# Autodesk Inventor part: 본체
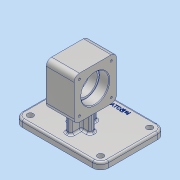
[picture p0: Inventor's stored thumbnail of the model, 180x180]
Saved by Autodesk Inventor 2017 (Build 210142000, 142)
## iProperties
Part Number: 본체
Material: 알루미늄 6061
Document SubType Name: Modeling
Designer: mrc
Density: 2.7 g/cm^3
Appearance: 알루미늄 - 평지
Mass: 683.214 g
Surface Area: 542.794 cm^2
Volume: 253.042 cm^3
Author: mrc
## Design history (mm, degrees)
sketch "스케치1"
  geometry: L1 (-65, -49)-(65, -49); L2 (65, -49)-(65, 49); L3 (65, 49)-(-65, 49); L4 (-65, 49)-(-65, -49); L5 (-65, -49)-(65, 49); L6 (65, -49)-(-65, 49); 1 further point
  constraints: 12 end point, 2 midpoint, 2 parallel, 1 horizontal, 1 perpendicular
  dimensions: "d0" = 130 distance of L2.end L3.end; "d1" = 98 distance of L1.end L2.end
extrude "돌출1" new body sketch "스케치1" distance "d2" = 10; taper "d3" = 0 deg
node "작업 평면1"
sketch "스케치2"
  geometry: L1 (-21, 19)-(21, 19); L2 (21, 19)-(21, -45); L3 (21, -45)-(-21, -45); L4 (-21, -45)-(-21, 19); L5 (-21, 19)-(21, -45); L6 (21, 19)-(-21, -45); L7 (65, -49)-(65, 49) reference; L8 (65, 49)-(-65, 49) reference; 2 further points
  constraints: 12 end point, 2 midpoint, 2 parallel, 1 horizontal, 1 perpendicular
  dimensions: "d5" = 42 distance of L1.start L1.end; "d6" = 64 distance of L1.end L2.end; "d7" = 65 distance from line of L7 point (0, -13); "d8" = 62 distance from line of L8 point (0, -13)
extrude "돌출2" join sketch "스케치2" distance "d9" = 64; taper "d10" = 0 deg
sketch "스케치3"
  geometry: L1 (-17, -9)-(17, -9); L2 (17, -9)-(17, -17); L3 (17, -17)-(-17, -17); L4 (-17, -17)-(-17, -9); L5 (-17, -9)-(17, -17); L6 (17, -9)-(-17, -17); L7 (65, -49)-(65, 49) reference; L8 (65, 49)-(-65, 49) reference; L9 (-4, 7)-(4, 7); L10 (4, 7)-(4, -33); L11 (4, -33)-(-4, -33); L12 (-4, -33)-(-4, 7); L13 (-4, 7)-(4, -33); L14 (4, 7)-(-4, -33); 3 further points
  constraints: 24 end point, 4 midpoint, 4 parallel, 2 horizontal, 2 perpendicular
  dimensions: "d11" = 34 distance of L2.end L3.end; "d12" = 8 distance of L3.end L1.start; "d13" = 65 distance from line of L7 point (0, -13); "d14" = 62 distance from line of L8 point (0, -13); "d15" = 40 distance of L9.end L10.end; "d16" = 8 distance of L10.end L11.end; "d17" = 65 distance from line of L7 point (0, -13); "d18" = 62 distance from line of L8 point (0, -13)
extrude "돌출3" join sketch "스케치3" stored distance "d19" = 64; taper "d20" = 0 deg
sketch "스케치4"
  geometry: L1 (64, 64)-(64, 0) reference; L2 (0, 64)-(0, 0) reference; C1 r 21 at (32, 32); 2 further points
  constraints: 1 centre point, 1 horizontal alignment, 1 midpoint
  dimensions: "d21" = 42 diameter of C1; "d22" = 32 distance from line of L2 C1.centre
extrude "돌출4" cut sketch "스케치4" distance "d23" = 15; taper "d24" = 0 deg
sketch "스케치5"
  geometry: C1 r 18 at (0, 0); C2 r 21 at (0, 0) reference; 1 further point
  constraints: 1 centre point, 1 concentric
  dimensions: "d25" = 36 diameter of C1
extrude "돌출5" cut sketch "스케치5" distance "d26" = 12; taper "d27" = 0 deg
sketch "스케치6"
  geometry: C1 r 21 at (-32, 32); C2 r 21 at (-32, 32) reference; 1 further point
  constraints: 1 centre point, 1 concentric
  dimensions: "d28" = 42 diameter of C1
extrude "돌출6" cut sketch "스케치6" distance "d29" = 15; taper "d30" = 0 deg
sketch "스케치9"
  geometry: L1 (-65, 49)-(-65, -49) reference; L2 (65, 49)-(-65, 49) reference; L3 (-65, -49)-(65, -49) reference; L4 (65, -49)-(65, 49) reference; C1 r 4.5 at (-53, 37); C2 r 4.5 at (-53, -37); C3 r 4.5 at (53, -37); C4 r 4.5 at (53, 37); 1 further point
  constraints: 4 centre point
  dimensions: "d42" = 9 diameter of C1; "d43" = 9 diameter of C2; "d44" = 9 diameter of C3; "d45" = 9 diameter of C4; "d46" = 12 distance from line of C1.centre L1; "d47" = 12 distance from line of L2 C1.centre; "d48" = 12 distance from line of L3 C2.centre; "d49" = 12 distance from line of L1 C2.centre; "d50" = 12 distance from line of C3.centre L3; "d51" = 12 distance from line of C3.centre L4; "d52" = 12 distance from line of L4 C4.centre; "d53" = 12 distance from line of C4.centre L2
extrude "돌출7" cut sketch "스케치9" distance "d54" = 10; taper "d55" = 0 deg
sketch "스케치10"
  geometry: L1 (0, 0)-(0, 64) reference; L2 (0, 64)-(-64, 64) reference; 2 further points
  dimensions: "d56" = 8 distance from line of L1 point (-8, 56); "d57" = 8 distance from line of point (-8, 56) L2
hole "구멍1" sketch "스케치10" at (-8, 56) diameter "d58" = 3.242; stored, may be unused: countersink angle "d62" = 90 deg, drill point angle "d64" = 118 deg; dims "d59" = 8, "d60" = 4, "d61" = 2, "d63" = 10
sketch "스케치11"
  geometry: L1 (0, 0)-(-64, 0) reference; L2 (0, 0)-(0, 64) reference; L3 (-64, 0)-(-64, 64) reference; L4 (0, 64)-(-64, 64) reference; 4 further points
  dimensions: "d65" = 8 distance from line of L1 point (-8, 8); "d66" = 8 distance from line of L2 point (-8, 8); "d67" = 8 distance from line of L3 point (-56, 8); "d68" = 8 distance from line of L1 point (-56, 8); "d69" = 8 distance from line of L3 point (-56, 56); "d70" = 8 distance from line of L4 point (-56, 56)
hole "구멍2" sketch "스케치11" at (-56, 56), (-56, 8), (-8, 8) diameter "d71" = 3.242; stored, may be unused: countersink angle "d75" = 90 deg, drill point angle "d77" = 118 deg; dims "d72" = 8, "d73" = 4, "d74" = 2, "d76" = 10
node "작업 평면2"
sketch "스케치12"
  geometry: L1 (65, 49)-(-65, 49) reference; 3 further points
  constraints: 1 midpoint, 1 vertical alignment, 1 other
  dimensions: "d79" = 10 distance from line of point (0, 39) L1
feature "엠보싱1" sketch "스케치12" dims "d0" = 130, "d1" = 98, "d80" = 0.5, "d81" = 0
fillet "모깎기1" dims "d82" = 8
fillet "모깎기2" dims "d83" = 12
fillet "모깎기3" dims "d84" = 3
chamfer "모따기1" distance "d85" = 1; stored, may be unused: second distance "d86" = 2, angle "d87" = 45 deg
chamfer "모따기2" distance "d88" = 1; stored, may be unused: second distance "d89" = 2, angle "d90" = 45 deg
fillet "모깎기4" dims "d91" = 3
fillet "모깎기5" dims "d92" = 3
fillet "모깎기6" dims "d93" = 3
fillet "모깎기7" dims "d94" = 0.3
node "솔리드1"
mirror "미러1"
other parameters: "d4" = 92, "d78" = 0
